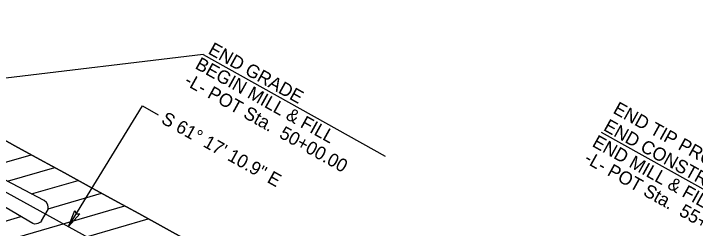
# Model space of a CAD drawing. Extents: x 1762196 to 1766326, y 709922 to 713142.
# Drawn here: x 1765429.5 to 1765791.9, y 710474.3 to 710588.2 of the extents above; entities that cross this region are included whole.
import ezdxf

# ---------------------------------------------------------------- set-up
doc = ezdxf.new("R2010")
doc.units = 0
for name, color, linetype in [('Old_Level_40', 7, 'Continuous'), ('Prop EOT', 7, 'Continuous'), ('Prop Horizontal Alignment', 7, 'Continuous'), ('Prop Horizontal Alignment Direction Label', 7, 'Continuous'), ('Prop Horizontal Alignment Station Label', 7, 'Continuous'), ('Prop Terminator CELL', 7, 'Continuous')]:
    doc.layers.add(name, color=color, linetype=linetype)

msp = doc.modelspace()

# ---------------------------------------------------------------- linework, layer by layer
at = {"layer": 'Old_Level_40'}
for p, q in [((1765413.37, 710505.96), (1765438.86, 710513.37)), ((1765426.18, 710499.27), (1765451.33, 710506.58)), ((1765438.98, 710492.58), (1765463.73, 710499.77)), ((1765447.78, 710484.72), (1765476.14, 710492.96)), ((1765424.25, 710467.47), (1765488.61, 710486.17)), ((1765414.27, 710474.98), (1765433.35, 710480.53)), ((1765429.7, 710458.64), (1765501.05, 710479.37))]:
    msp.add_line(p, q, dxfattribs=at)
msp.add_lwpolyline([(1765390.11, 710557.6), (1765390.07, 710554.8), (1765390.44, 710550.16), (1765391.59, 710546.28), (1765393.56, 710542.79), (1765395.95, 710539.7), (1765399.01, 710537.09), (1765402.08, 710534.52), (1765404.67, 710532.73), (1765417.04, 710525.3), (1765430.2, 710518.11), (1765443.35, 710510.91), (1765456.53, 710503.76), (1765469.69, 710496.46), (1765482.87, 710489.3), (1765496.03, 710482.11), (1765509.19, 710474.92), (1765522.3, 710467.65)], dxfattribs=at)
at = {"layer": 'Prop EOT'}
msp.add_line((1765444.29, 710478.29), (1765447.76, 710484.27), dxfattribs=at)
for points in [[(1765522.3, 710467.65), (1765509.19, 710474.92), (1765496.03, 710482.11), (1765482.87, 710489.3), (1765469.69, 710496.46), (1765456.53, 710503.76), (1765443.35, 710510.91), (1765430.2, 710518.11), (1765417.04, 710525.3), (1765404.67, 710532.73), (1765402.08, 710534.52), (1765399.01, 710537.09), (1765395.95, 710539.7), (1765393.56, 710542.79), (1765391.59, 710546.28), (1765390.44, 710550.16), (1765390.07, 710554.8), (1765390.11, 710557.6)], [(1765447.76, 710484.27), (1765447.82, 710485.54), (1765447.62, 710486.71), (1765446.96, 710488.01), (1765445.71, 710489.06), (1765431.92, 710496.26), (1765418.63, 710503.22), (1765405.32, 710510.17), (1765392.02, 710517.13), (1765379.28, 710523.73)], [(1765444.29, 710478.29), (1765443.72, 710477.62), (1765443.08, 710477.16), (1765442.37, 710476.81), (1765441.59, 710476.62), (1765440.65, 710476.6), (1765439.76, 710476.79), (1765425.44, 710485.14), (1765412.49, 710492.69), (1765399.52, 710500.23), (1765386.6, 710507.82), (1765374.48, 710514.96)]]:
    msp.add_lwpolyline(points, dxfattribs=at)
at = {"layer": 'Prop Horizontal Alignment'}
msp.add_line((1765252.32, 710588.23), (1765788.26, 710294.65), dxfattribs=at)
at = {"layer": 'Prop Horizontal Alignment Station Label'}
for p, q in [((1765530.21, 710566.51), (1765334.53, 710543.2)), ((1765530.21, 710566.51), (1765627.03, 710512.6)), ((1765458.64, 710475.21), (1765497.97, 710539.25)), ((1765497.97, 710539.25), (1765506.33, 710534.59)), ((1765741.89, 710525.28), (1765859.08, 710460.02))]:
    msp.add_line(p, q, dxfattribs=at)
at = {"layer": 'Prop Terminator CELL'}
msp.add_lwpolyline([(1765464.67, 710482.07), (1765458.64, 710475.21), (1765462.01, 710483.76), (1765462.77, 710481.94)], close=True, dxfattribs=at)

# ---------------------------------------------------------------- texts
at = {"layer": 'Prop Horizontal Alignment Direction Label'}
msp.add_text('S 61%%d 17\' 10.9" E', height=7, rotation=330.8436, dxfattribs=at).set_placement((1765507.39, 710530.46))
at = {"layer": 'Prop Horizontal Alignment Station Label'}
for s, p in [('END GRADE ', (1765532.39, 710567.26)), ('BEGIN MILL & FILL', (1765525.48, 710559.4)), ('-L- POT Sta.  50+00.00', (1765519.74, 710550.86)), ('END TIP PROJECT U-5743', (1765747.68, 710535.76)), ('END CONSTRUCTION', (1765742.57, 710526.58)), ('END MILL & FILL', (1765736.57, 710518.1)), ('-L- POT Sta.  55+00.00', (1765732.31, 710509.57))]:
    msp.add_text(s, height=7, rotation=330.8875, dxfattribs=at).set_placement(p)

doc.saveas('drawing.dxf')
